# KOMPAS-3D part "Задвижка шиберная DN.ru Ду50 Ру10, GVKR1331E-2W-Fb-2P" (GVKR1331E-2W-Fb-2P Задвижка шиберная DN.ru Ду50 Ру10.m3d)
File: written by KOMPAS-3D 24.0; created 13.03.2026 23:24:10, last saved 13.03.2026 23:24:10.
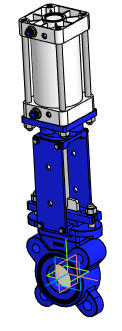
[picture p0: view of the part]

Document properties: Автор: DN.RU; Полное имя файла: D:\PROJECT CAD\DN.RU\...192.(ACTUALE) GVKR1331E-2W-Fb-2P Задвижка шиберная DN.ru Ру6-10\DN50\GVKR1331E-2W-Fb-2P Задвижка шиберная DN.ru Ду50 Ру10.m3d

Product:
- Body: Твердое тело1  | qty 1
    Масса: 15.74714
- Part/product: Задвижка шиберная DN.ru Ду50 Ру10  | designation GVKR1331E-2W-Fb-2P
    Масса: 9
    Раздел спецификации: Прочие изделия
    Комментарий: D040-07406
    Примечание: D040-07406
    additional columns: Чугун, серый

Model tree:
1. Твердое тело1  (labels: Твердое тело1)

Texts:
  GVKR1331E-2W-Fb-2P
